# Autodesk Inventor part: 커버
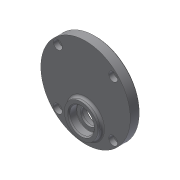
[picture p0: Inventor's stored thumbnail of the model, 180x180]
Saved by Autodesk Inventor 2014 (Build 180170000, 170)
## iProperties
Created: 2014-12
Part Number: 커버
Material: Generic
Document SubType Name: Modeling
Designer: MYHOME
Density: 1 g/cm^3
Appearance: Default
Author: MYHOME
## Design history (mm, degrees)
sketch "스케치1"
  geometry: C1 r 40 at (0, 0); 1 further point
  constraints: 1 centre point, 1 coincident
  dimensions: "d0" = 80 diameter of C1
extrude "돌출1" new body sketch "스케치1" distance "d1" = 9; taper "d2" = 0 deg
sketch "스케치2"
  geometry: C1 r 40 at (0, 0) reference; C2 r 15 at (0, -20)
  constraints: 1 centre point, 1 vertical alignment
  dimensions: "d3" = 30 diameter of C2; "d4" = 20 distance of C2.centre C1.centre
extrude "돌출2" join sketch "스케치2" distance "d5" = 4; taper "d6" = 0 deg
sketch "스케치3"
  geometry: C1 r 40 at (0, 0) reference; C2 r 14 at (0, 11); C3 r 14 at (0, -20)
  constraints: 2 centre point, 2 vertical alignment
  dimensions: "d7" = 28 diameter of C2; "d8" = 28 diameter of C3; "d9" = 11 distance of C1.centre C2.centre; "d10" = 20 distance of C3.centre C1.centre
extrude "돌출3" join sketch "스케치3" distance "d11" = 3; taper "d12" = 0 deg
sketch "스케치4"
  geometry: C1 r 14 at (0, 0) reference; C2 r 11 at (0, 0); 1 further point
  constraints: 1 centre point, 1 coincident
  dimensions: "d13" = 22 diameter of C2
extrude "돌출4" cut sketch "스케치4" distance "d14" = 7; taper "d15" = 0 deg
sketch "스케치5"
  geometry: C1 r 9 at (0, 0); 2 further points
  constraints: 1 centre point, 1 coincident, 1 vertical alignment
  dimensions: "d16" = 18 diameter of C1
extrude "돌출5" cut sketch "스케치5" distance "d17" = 1; taper "d18" = 0 deg
fillet "모깎기1" dims "d19" = 0.3
fillet "모깎기2" dims "d20" = 2
chamfer "모따기1" distance "d21" = 1; stored, may be unused: second distance "d22" = 2, angle "d23" = 45 deg
sketch "스케치6"
  geometry: C1 r 14 at (0, 0) reference; C2 r 11 at (0, 0); 1 further point
  constraints: 1 centre point, 1 coincident
  dimensions: "d24" = 22 diameter of C2
extrude "돌출6" cut sketch "스케치6" distance "d25" = 7; taper "d26" = 0 deg
sketch "스케치7"
  geometry: C1 r 11 at (0, 0) reference; C2 r 7.5 at (0, 0); 1 further point
  constraints: 1 centre point, 1 coincident
  dimensions: "d27" = 15 diameter of C2
extrude "돌출7" cut sketch "스케치7" distance "d28" = 2; taper "d29" = 0 deg
sketch "스케치8"
  geometry: C1 r 15 at (0, 0) reference; C2 r 11 at (0, 0); 1 further point
  constraints: 1 centre point, 1 coincident
  dimensions: "d30" = 22 diameter of C2
extrude "돌출8" cut sketch "스케치8" distance "d31" = 7; taper "d32" = 0 deg
fillet "모깎기3" dims "d33" = 0.3
chamfer "모따기2" distance "d34" = 1; stored, may be unused: second distance "d35" = 2, angle "d36" = 45 deg
fillet "모깎기4" dims "d37" = 2
sketch "스케치9"
  geometry: L1 (24.749, 24.749)-(-24.749, -24.749); L2 (-24.749, 24.749)-(24.749, -24.749); L3 (-35, 0)-(35, 0); C1 r 40 at (0, 0) reference; A1 r 35 centre (0, 0) between (-24.749, -24.749) and (-24.749, 24.749); 5 further points
  constraints: 6 end point, 5 coincident, 5 point on circle, 4 midpoint, 1 centre point, 1 horizontal
  dimensions: "d38" = 70 diameter of A1; "d39" = 45 deg angle of L1 L3; "d40" = 90 deg angle of L2 L1
hole "구멍1" sketch "스케치9" at (-24.749, 24.749), (24.749, 24.749), (24.749, -24.749), (-24.749, -24.749) diameter "d41" = 4.5; stored, may be unused: countersink angle "d45" = 90 deg, drill point angle "d47" = 118 deg; dims "d42" = 6, "d43" = 8, "d44" = 4.4, "d46" = 8
chamfer "모따기3" distance "d48" = 1; stored, may be unused: second distance "d49" = 2, angle "d50" = 45 deg
node "솔리드1"
